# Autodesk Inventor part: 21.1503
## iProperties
Created: 2006-12
Part Number: 21.1503
Material: Steel, Mild
Description: M5x16 C'SUNK
Document SubType Name: Modeling
Standard: DIN 7991
Designer: Andy Moles
Standards Organization: DIN
Language: en-US
Size Designation: M5x16
Categories: <MemberInstance Version="R10.0.0"><Categories><Category DisplayName="Fasteners" InternalName="e4da775c-781d-43d5-af7c-5136215cf5a6" Mnemonic="FSTN"><Category Di
Density: 7.86 g/cm^3
Mass: 2.97248 g
Surface Area: 4.18131 cm^2
Volume: 0.378178 cm^3
Vendor: S
Author: Andy Moles
Revision Number: 1
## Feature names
1. Revolution1
2. Extrusion1
3. Fillet1
4. Chamfer1
